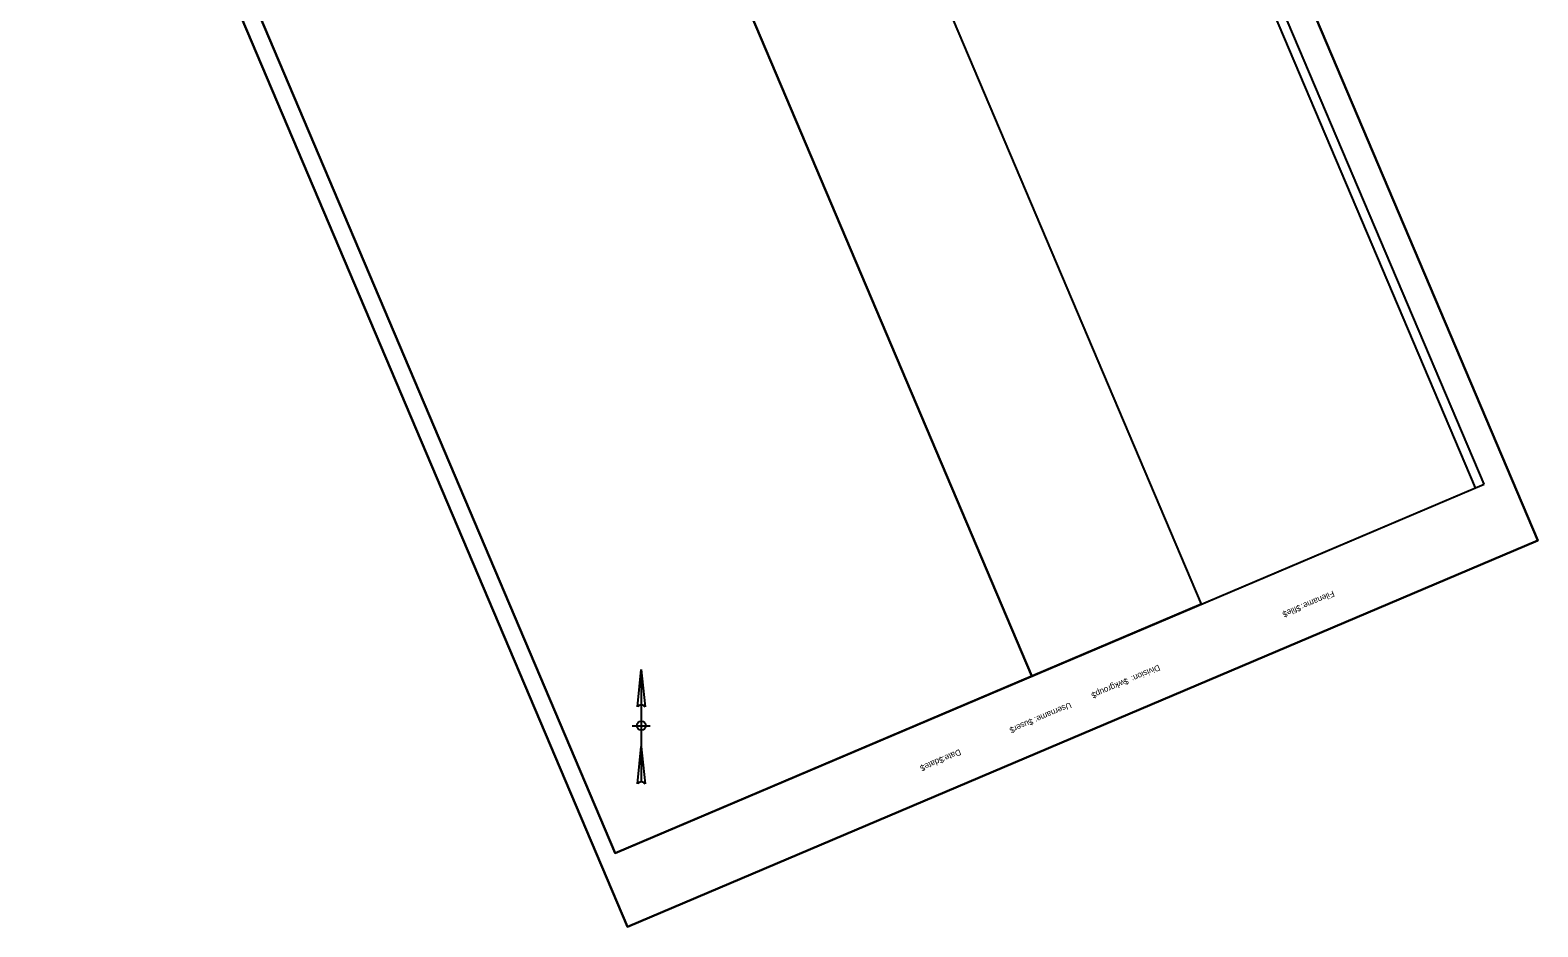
# Model space of a CAD drawing. Extents: x 1036681 to 1037519, y 782967 to 783965.
# Drawn here: x 1036681 to 1037519, y 782967 to 783466 of the extents above; entities that cross this region are included whole.
import ezdxf

# ---------------------------------------------------------------- set-up
doc = ezdxf.new("R2010")
doc.units = 0
for name, color, linetype in [('CLIPS', 7, 'Continuous'), ('Default', 7, 'Continuous'), ('PLOT BOUNDARY', 7, 'Continuous')]:
    doc.layers.add(name, color=color, linetype=linetype)

msp = doc.modelspace()

# ---------------------------------------------------------------- linework, layer by layer
at = {"layer": 'CLIPS'}
for points in [[(1037484.43, 783211.63), (1037191.38, 783902.01), (1036944.68, 783797.29), (1037237.73, 783106.91)], [(1037005.88, 783008.5), (1036712.83, 783698.87), (1037038.7, 783837.2), (1037331.75, 783146.82)], [(1037237.73, 783106.91), (1036944.68, 783797.29), (1036712.83, 783698.88), (1037005.88, 783008.5)]]:
    msp.add_lwpolyline(points, close=True, dxfattribs=at)
at = {"layer": 'Default'}
for p, q in [((1037489.14, 783213.63), (1037176.56, 783950.03)), ((1036693.3, 783744.9), (1037005.88, 783008.5)), ((1037005.88, 783008.5), (1037489.14, 783213.63)), ((1037018.4, 783089.75), (1037020.49, 783110.58)), ((1037020.49, 783110.58), (1037020.49, 783048.08)), ((1037020.49, 783110.58), (1037022.57, 783089.75)), ((1037015.49, 783079.33), (1037025.49, 783079.33)), ((1037018.4, 783046.97), (1037020.49, 783067.8)), ((1037020.49, 783067.8), (1037022.57, 783046.97))]:
    msp.add_line(p, q, dxfattribs=at)
msp.add_lwpolyline([(1037519.04, 783182.36), (1037186.91, 783964.78), (1036680.64, 783749.88), (1037012.76, 782967.45)], close=True, dxfattribs=at)
msp.add_circle((1037020.49, 783079.33), 2.5, dxfattribs=at)
for centre in [(1037020.49, 783088.37), (1037020.49, 783045.58)]:
    msp.add_arc(centre, 2.5, 33.55731, 146.44269, dxfattribs=at)
at = {"layer": 'PLOT BOUNDARY'}
msp.add_lwpolyline([(1037012.76, 782967.45), (1036680.64, 783749.88), (1037186.91, 783964.78), (1037519.04, 783182.36)], close=True, dxfattribs=at)

# ---------------------------------------------------------------- texts
at = {"layer": 'Default'}
for s, p in [('Filename:', (1037405.07, 783154.5)), ('$file$', (1037386.54, 783146.64)), ('$wkgroup$', (1037290.6, 783105.91)), ('Division:', (1037308.11, 783113.35)), ('Username:', (1037258.85, 783092.44)), ('$user$', (1037237.57, 783083.4)), ('Date:', (1037197.41, 783066.36)), ('$date$', (1037187.8, 783062.28))]:
    msp.add_text(s, height=3.348, rotation=203, dxfattribs=at).set_placement(p)

doc.saveas('drawing.dxf')
